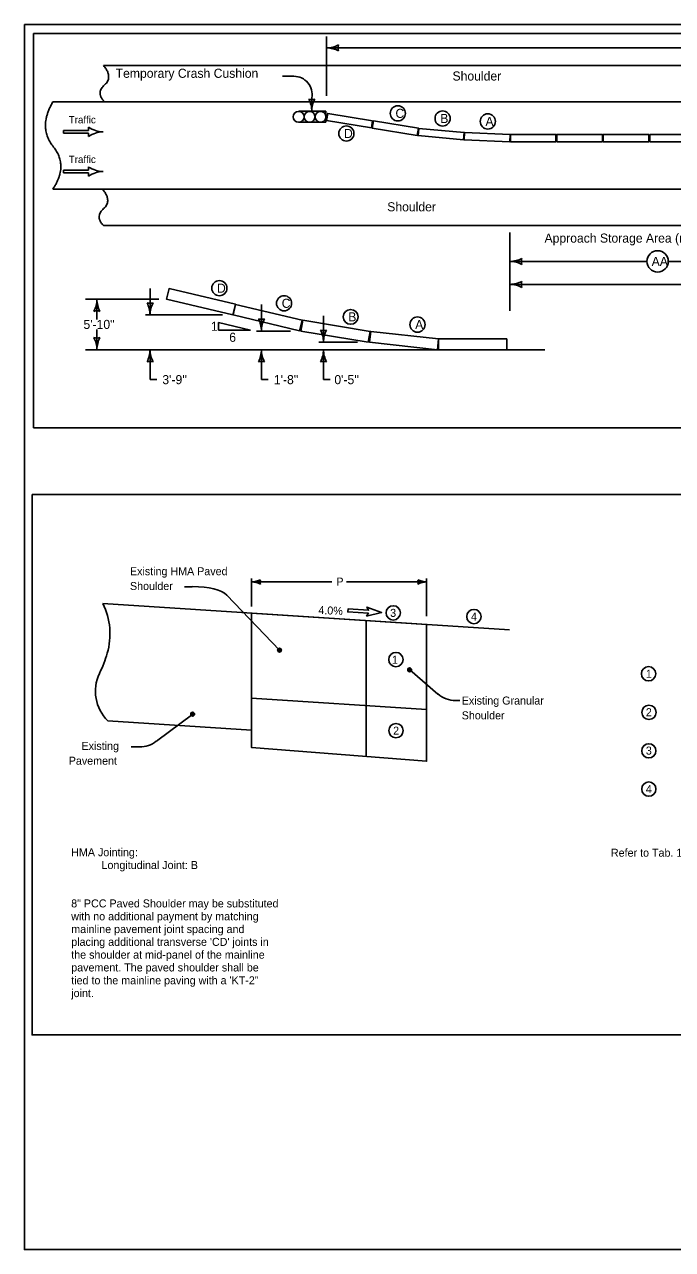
# Model space of a CAD drawing. Extents: x 8045 to 81668, y 6217 to 16762.
# Drawn here: x 13733 to 14801, y 7924 to 9944 of the extents above; entities that cross this region are included whole.
import ezdxf

# ---------------------------------------------------------------- set-up
doc = ezdxf.new("R2010")
doc.units = 0
for name, color, linetype in [('dsnNonPlotable', 7, 'Continuous'), ('dsnStdBlock', 7, 'Continuous'), ('dsnStdBlockModified', 7, 'Continuous'), ('dsnStdBorder', 7, 'Continuous'), ('dsnStdLineWork', 7, 'Continuous'), ('dsnStdNameDate', 7, 'Continuous'), ('dsnStdSection', 7, 'Continuous'), ('Level 5', 7, 'Continuous')]:
    doc.layers.add(name, color=color, linetype=linetype)

msp = doc.modelspace()

# ---------------------------------------------------------------- linework, layer by layer
at = {"layer": 'dsnNonPlotable'}
for p, q in [((14230.5, 9924.1), (14230.5, 9826.6)), ((14230.5, 9905.4), (15109, 9905.4)), ((13862.8, 9876.4), (14991.3, 9876.4)), ((14176.7, 9858.7), (14158, 9858.7)), ((14206.2, 9823.4), (14206.2, 9800.9)), ((13779.2, 9816.4), (15021.3, 9816.4)), ((14184.6, 9800.9), (14229.6, 9800.9)), ((14229.6, 9800.9), (14229.6, 9782.8)), ((14229.6, 9782.8), (14184.6, 9782.8)), ((14228.4, 9788.6), (14229.7, 9788.3)), ((14230.1, 9784.9), (14230.1, 9784.9)), ((13838.1, 9769.3), (13796.8, 9769.3)), ((13796.8, 9769.3), (13796.8, 9764.8)), ((13796.8, 9764.8), (13838.1, 9764.8)), ((13838.1, 9774.5), (13838.1, 9769.3)), ((13838.1, 9764.8), (13838.1, 9759.5)), ((13862, 9767), (13862, 9767)), ((13838.1, 9703.8), (13796.8, 9703.8)), ((13796.8, 9703.8), (13796.8, 9699.3)), ((13796.8, 9699.3), (13838.1, 9699.3)), ((13838.1, 9709.1), (13838.1, 9703.8)), ((13838.1, 9699.3), (13838.1, 9694.1)), ((13862, 9701.6), (13862, 9701.6)), ((13779.2, 9672.4), (15021.3, 9672.4)), ((13862.8, 9612.4), (14991.3, 9612.4)), ((14532.6, 9601.2), (14532.6, 9472)), ((14532.6, 9553.4), (14758.7, 9553.4)), ((14794, 9553.4), (15020.1, 9553.4)), ((14532.6, 9515.5), (15123.4, 9515.5)), ((13939.5, 9508.5), (13939.5, 9465)), ((13954.1, 9491), (13832.9, 9491)), ((13851.9, 9491), (13851.9, 9457.5)), ((14123.1, 9482.1), (14123.1, 9438.6)), ((14059, 9465), (13931.8, 9465)), ((14225.5, 9463.5), (14225.5, 9420.1)), ((13851.9, 9441.2), (13851.9, 9407.7)), ((14170.9, 9438.6), (14115.3, 9438.6)), ((14281.8, 9420.1), (14217.7, 9420.1)), ((14590.3, 9407.7), (13832.9, 9407.7)), ((13939.5, 9407.7), (13939.5, 9358.5)), ((14123.1, 9407.7), (14123.1, 9358.5)), ((14225.5, 9407.7), (14225.5, 9380.8)), ((14225.5, 9380.8), (14225.5, 9358.5)), ((13939.5, 9358.5), (13950.7, 9358.5)), ((14123.1, 9358.5), (14134.3, 9358.5)), ((14225.5, 9358.5), (14236.6, 9358.5))]:
    msp.add_line(p, q, dxfattribs=at)
for points in [[(14306.4, 9785.3), (14232.4, 9797.4), (14230.5, 9785.6), (14304.5, 9773.4)], [(14381.9, 9772.9), (14307.9, 9785), (14306, 9773.2), (14380, 9761)], [(14457.3, 9765.7), (14382.7, 9772.8), (14381.5, 9760.8), (14456.2, 9753.7)], [(14533.1, 9762.7), (14458.2, 9765.7), (14457.7, 9753.7), (14532.6, 9750.7)], [(14533.8, 9762.7), (14608.8, 9762.7), (14608.8, 9750.7), (14533.8, 9750.7)], [(14610.3, 9762.7), (14685.3, 9762.7), (14685.3, 9750.7), (14610.3, 9750.7)], [(14686.8, 9762.7), (14761.8, 9762.7), (14761.8, 9750.7), (14686.8, 9750.7)], [(14763.3, 9762.7), (14838.3, 9762.7), (14838.3, 9750.7), (14763.3, 9750.7)], [(14080.3, 9482.6), (13970.9, 9508.5), (13966.7, 9491), (14076.2, 9465.1)], [(14190.1, 9456.6), (14080.6, 9482.5), (14076.5, 9465), (14186, 9439.1)], [(14302.2, 9437.9), (14191.2, 9456.4), (14188.3, 9438.6), (14299.2, 9420.2)], [(14415.3, 9425.6), (14303.5, 9437.9), (14301.5, 9420.1), (14413.3, 9407.7)], [(14527.8, 9425.7), (14415.3, 9425.7), (14415.3, 9407.7), (14527.8, 9407.7)]]:
    msp.add_lwpolyline(points, close=True, dxfattribs=at)
for centre, radius in [((14184.6, 9791.8), 9), ((14184.6, 9791.8), 9), ((14202.6, 9791.8), 9), ((14202.6, 9791.8), 9), ((14220.6, 9791.8), 9), ((14220.6, 9791.8), 9), ((14348.1, 9797.5), 12.5), ((14421.9, 9789.1), 12.5), ((14263.2, 9764.3), 12.5), ((14496.4, 9784.2), 12.5), ((14776.4, 9553.4), 17.6), ((14053.8, 9509.2), 12.5), ((14160.5, 9484.3), 12.5), ((14270.2, 9461.9), 12.2), ((14380.5, 9449.2), 12.5)]:
    msp.add_circle(centre, radius, dxfattribs=at)
for centre, radius, start, end in [((14230.5, 9947.9), 42.5, 270, 298.0725), ((14230.5, 9862.9), 42.5, 61.9275, 90), ((14266.1, 9905.4), 16.4, 162.2666, 197.7334), ((14176.7, 9828.7), 30, 349.6463, 90), ((14206.2, 9836.5), 16.4, 252.2666, 287.7333), ((14163.7, 9800.9), 42.5, 360, 28.0725), ((14248.7, 9800.9), 42.5, 151.9275, 180), ((13864, 9815.4), 48.4, 237.618, 267.648), ((13864, 9718.7), 48.4, 92.352, 122.382), ((13864, 9749.9), 48.4, 237.618, 267.648), ((13864, 9653.3), 48.4, 92.352, 122.382), ((14532.6, 9595.9), 42.5, 270, 298.0725), ((14568.3, 9553.4), 16.4, 162.2666, 197.7334), ((14532.6, 9510.9), 42.5, 61.9275, 90), ((14532.6, 9558), 42.5, 270, 298.0725), ((14532.6, 9473), 42.5, 61.9275, 90), ((14568.3, 9515.5), 16.4, 162.2666, 197.7334), ((13809.4, 9491), 42.5, 331.9275, 0), ((13894.4, 9491), 42.5, 180, 208.0725), ((13939.5, 9500.7), 16.4, 252.2666, 287.7334), ((13897, 9465), 42.5, 0, 28.0725), ((13982, 9465), 42.5, 151.9275, 180), ((13851.9, 9455.4), 16.4, 72.2666, 107.7334), ((14123.1, 9474.3), 16.4, 252.2666, 287.7334), ((14080.6, 9438.6), 42.5, 0, 28.0725), ((14165.6, 9438.6), 42.5, 151.9275, 180), ((14225.5, 9455.7), 16.4, 252.2666, 287.7334), ((14183, 9420.1), 42.5, 0, 28.0725), ((14268, 9420.1), 42.5, 151.9275, 180), ((13851.9, 9443.4), 16.4, 252.2666, 287.7334), ((13809.4, 9407.7), 42.5, 0, 28.0725), ((13894.4, 9407.7), 42.5, 151.9275, 180), ((13897, 9407.7), 42.5, 331.9275, 0), ((13982, 9407.7), 42.5, 180, 208.0725), ((14080.6, 9407.7), 42.5, 331.9275, 0), ((14165.6, 9407.7), 42.5, 180, 208.0725), ((14183, 9407.7), 42.5, 331.9275, 0), ((14268, 9407.7), 42.5, 180, 208.0725), ((13939.5, 9372.1), 16.4, 72.2666, 107.7334), ((14123.1, 9372.1), 16.4, 72.2666, 107.7334), ((14225.5, 9372.1), 16.4, 72.2666, 107.7334)]:
    msp.add_arc(centre, radius, start, end, dxfattribs=at)
for points in [[(13862.8, 9876.4), (13878.9, 9857.1), (13850, 9831.5), (13864.4, 9816.5)], [(13779.2, 9816.4), (13754.6, 9773.8), (13805.3, 9711.6), (13779.2, 9672.4)], [(13861.2, 9672.4), (13877.3, 9653.1), (13848.4, 9627.5), (13862.8, 9612.4)]]:
    msp.add_open_spline(points, degree=2, dxfattribs=at)
at = {"layer": 'dsnStdBlock'}
msp.add_line((13747.5, 9929), (13747.5, 9929), dxfattribs=at)
at = {"layer": 'dsnStdBlockModified'}
for p, q in [((13747.5, 9929), (16852.5, 9929)), ((13747.5, 9279), (13747.5, 9929))]:
    msp.add_line(p, q, dxfattribs=at)
at = {"layer": 'dsnStdBorder'}
msp.add_line((16852.5, 9279), (13747.5, 9279), dxfattribs=at)
at = {"layer": 'dsnStdLineWork'}
for p, q in [((14107, 8984.2), (14107, 9030.4)), ((14395.5, 8968.1), (14395.5, 9030.4)), ((13996.4, 9017), (14009.1, 9017)), ((14107, 9024.9), (14239.3, 9024.9)), ((14107.1, 9024.9), (14120.9, 9024.9)), ((14263.2, 9024.9), (14395.5, 9024.9)), ((14395.5, 9024.9), (14381.7, 9024.9)), ((13861.7, 8989.1), (14532, 8945.8)), ((14066.1, 9003.2), (14153.2, 8912.4)), ((14295.8, 8736.8), (14295.8, 8961)), ((14414.1, 8840), (14367.8, 8879.7)), ((14107, 8832.9), (14395.5, 8814.2)), ((14450.3, 8829.2), (14443.4, 8829.2)), ((13869.8, 8795.8), (14107, 8780.5)), ((13949.9, 8762), (14009.9, 8807)), ((13922.4, 8752.7), (13908.4, 8752.7))]:
    msp.add_line(p, q, dxfattribs=at)
for points in [[(14120.6, 9022.3), (14120.1, 9024.9), (14120.6, 9027.5), (14117.5, 9026), (14112.6, 9024.9), (14117.9, 9023.6), (14120.2, 9022.6), (14119.6, 9024.9), (14119.8, 9026.5), (14117.8, 9025.6), (14115.1, 9024.9), (14118, 9024), (14119.5, 9023.5), (14119.2, 9025.7), (14117.2, 9024.9), (14118.8, 9024.4), (14118.8, 9025.1), (14118.1, 9024.9)], [(14382, 9027.4), (14382.5, 9024.8), (14382, 9022.2), (14385.1, 9023.7), (14390, 9024.8), (14384.7, 9026.1), (14382.4, 9027.1), (14383, 9024.8), (14382.8, 9023.2), (14384.8, 9024.1), (14387.5, 9024.8), (14384.6, 9025.7), (14383.1, 9026.2), (14383.4, 9024), (14385.4, 9024.8), (14383.8, 9025.3), (14383.8, 9024.6), (14384.5, 9024.8)], [(14107, 8973.5), (14107, 8751.6), (14395.5, 8729), (14395.5, 8954.6)], [(14155.2, 8914.1), (14154.2, 8914.5), (14152.6, 8915.3), (14151.2, 8914.3), (14150.3, 8913.1), (14150.1, 8911.4), (14151.3, 8910.4), (14152.7, 8909.4), (14154.2, 8909.8), (14155.3, 8910.7), (14155.8, 8912.6), (14155.1, 8913.6), (14153.6, 8914.5), (14151.9, 8914.7), (14150.8, 8913.5), (14150.7, 8911.9), (14151.6, 8910.7), (14153, 8909.8), (14153.9, 8910.3), (14154.9, 8910.8), (14155.3, 8912.4), (14154.5, 8913.2), (14153.3, 8914), (14152.1, 8914.2), (14151.5, 8912.8), (14151.6, 8911.5), (14152.6, 8910.5), (14153.3, 8910.8), (14154.3, 8911.1), (14154.5, 8912.3), (14154, 8913.2), (14153, 8913.5), (14152.2, 8912.9), (14152.1, 8912), (14152.6, 8911.2), (14153.1, 8911.1), (14153.7, 8911.3), (14154, 8912.3), (14153.6, 8912.8), (14152.9, 8913), (14152.6, 8912.5), (14152.7, 8912), (14153.1, 8911.5), (14153.4, 8911.8), (14153.2, 8912.4)], [(14369.7, 8881.7), (14368.6, 8882.1), (14367.1, 8882.9), (14365.7, 8881.9), (14364.8, 8880.7), (14364.6, 8879), (14365.8, 8878), (14367.1, 8877), (14368.6, 8877.4), (14369.7, 8878.3), (14370.3, 8880.2), (14369.6, 8881.2), (14368.1, 8882.1), (14366.4, 8882.3), (14365.3, 8881.1), (14365.2, 8879.5), (14366.1, 8878.4), (14367.5, 8877.4), (14368.3, 8877.9), (14369.4, 8878.4), (14369.8, 8880), (14368.9, 8880.8), (14367.8, 8881.6), (14366.5, 8881.8), (14365.9, 8880.4), (14366.1, 8879.1), (14367, 8878.1), (14367.8, 8878.4), (14368.7, 8878.7), (14369, 8879.9), (14368.5, 8880.8), (14367.5, 8881.1), (14366.7, 8880.5), (14366.5, 8879.6), (14367, 8878.8), (14367.6, 8878.7), (14368.2, 8878.9), (14368.4, 8879.9), (14368.1, 8880.4), (14367.3, 8880.6), (14367, 8880.1), (14367.1, 8879.6), (14367.6, 8879.1), (14367.9, 8879.5), (14367.7, 8880)], [(14011.9, 8808.7), (14010.8, 8809.1), (14009.3, 8809.9), (14007.9, 8808.9), (14007, 8807.7), (14006.8, 8806), (14008, 8805), (14009.3, 8804), (14010.8, 8804.3), (14011.9, 8805.2), (14012.5, 8807.2), (14011.8, 8808.2), (14010.3, 8809), (14008.6, 8809.3), (14007.5, 8808.1), (14007.4, 8806.5), (14008.3, 8805.3), (14009.7, 8804.4), (14010.6, 8804.9), (14011.6, 8805.4), (14012, 8806.9), (14011.1, 8807.8), (14010, 8808.6), (14008.7, 8808.7), (14008.1, 8807.4), (14008.3, 8806.1), (14009.2, 8805.1), (14010, 8805.4), (14010.9, 8805.7), (14011.2, 8806.9), (14010.7, 8807.8), (14009.7, 8808.1), (14008.9, 8807.4), (14008.7, 8806.6), (14009.2, 8805.7), (14009.8, 8805.7), (14010.4, 8805.9), (14010.6, 8806.8), (14010.3, 8807.4), (14009.6, 8807.6), (14009.2, 8807.1), (14009.3, 8806.5), (14009.8, 8806.1), (14010.1, 8806.4), (14009.9, 8807)]]:
    msp.add_lwpolyline(points, dxfattribs=at)
for points in [[(14107, 8973.5), (14395.5, 8954.6), (14395.5, 8814.2), (14107, 8832.9)], [(14296.3, 8968.2), (14321.3, 8974.4), (14297.2, 8983.4), (14299.8, 8978.2), (14266, 8980.4), (14265.6, 8975.3), (14299.5, 8973.1)]]:
    msp.add_lwpolyline(points, close=True, dxfattribs=at)
for centre, radius in [((14340.5, 8973.8), 11.8), ((14473.5, 8967.7), 11.8), ((14153, 8912.2), 3.15), ((14344.9, 8896.8), 11.8), ((14367.5, 8879.8), 3.15), ((14761.5, 8873.4), 11.8), ((14009.7, 8806.8), 3.15), ((14762.1, 8809.7), 11.8), ((14345, 8779.6), 11.8), ((14761.9, 8746.3), 11.8), ((14761.9, 8683.2), 11.8)]:
    msp.add_circle(centre, radius, dxfattribs=at)
for centre, radius, start, end in [((14107.1, 9055.5), 30.6, 270, 298.0725), ((14107.1, 8994.3), 30.6, 61.9275, 90), ((14132.7, 9024.9), 11.8, 162.2666, 197.7334), ((14369.9, 9024.9), 11.8, 342.2666, 17.7334), ((14395.5, 9055.5), 30.6, 241.9275, 270), ((14395.5, 8994.3), 30.6, 90, 118.0725), ((13760.4, 8939), 113, 343.6708, 26.3373), ((13656.4, 8969.5), 221.4, 334.4332, 343.6708), ((13917.6, 8844.5), 68.2, 154.4332, 225.5564), ((14443.4, 8874.2), 45, 229.3882, 270), ((13922.4, 8797.7), 45, 270, 307.6187)]:
    msp.add_arc(centre, radius, start, end, dxfattribs=at)
msp.add_ellipse((13953.9, 8972), major_axis=(-116.2, -24), ratio=0.327877, start_param=3.345066, end_param=4.150713, dxfattribs=at)
at = {"layer": 'dsnStdNameDate'}
msp.add_lwpolyline([(13745, 9169.2), (15295.8, 9169.2), (15295.8, 8277.8), (13745, 8277.8)], close=True, dxfattribs=at)
at = {"layer": 'dsnStdSection'}
msp.add_lwpolyline([(13732.5, 9944), (16867.5, 9944), (16867.5, 7924), (13732.5, 7924)], close=True, dxfattribs=at)
at = {"layer": 'Level 5'}
for p, q in [((14105.1, 9440.1), (14052.5, 9452.5)), ((14052.5, 9452.5), (14052.5, 9440.1)), ((14052.5, 9440.1), (14105.1, 9440.1))]:
    msp.add_line(p, q, dxfattribs=at)

# ---------------------------------------------------------------- texts
at = {"layer": 'dsnStdLineWork'}
for s, p in [('Existing HMA Paved', (13906.4, 9035.9)), ('P', (14246.7, 9018.8)), ('Shoulder', (13906.4, 9011.5)), ('3', (14335.4, 8967.2)), ('4', (14468.7, 8961.1)), ('1', (14338.4, 8889.9)), ('1', (14757, 8866.8)), ('Existing Granular', (14453.4, 8822.6)), ('Shoulder', (14453.4, 8798.2)), ('2', (14757, 8803.4)), ('2', (14340.3, 8773)), ('Existing', (13826.5, 8747.8)), ('3', (14757, 8740.1)), ('Pavement', (13805.5, 8723.4)), ('4', (14757, 8676.7)), ('HMA Jointing:', (13809.5, 8572.5)), ('Refer to Tab. 112-9 for P width and Shoulder quantities', (14699.4, 8571.7)), ('Longitudinal Joint: B', (13859.5, 8551.4)), ('8" PCC Paved Shoulder may be substituted', (13809.5, 8488.1)), ('with no additional payment by matching ', (13809.5, 8466.9)), ('mainline pavement joint spacing and ', (13809.6, 8445.8)), ("placing additional transverse 'CD' joints in ", (13809.6, 8424.7)), ('the shoulder at mid-panel of the mainline ', (13809.6, 8403.6)), ('pavement. The paved shoulder shall be ', (13809.6, 8382.5)), ('tied to the mainline paving with a \'KT-2" ', (13809.6, 8361.3)), ('joint.', (13809.6, 8340.2))]:
    msp.add_text(s, height=13.2, dxfattribs=at).set_placement(p)
msp.add_text('4.0%', height=13.2, rotation=357.4961, dxfattribs=at).set_placement((14216.8, 8972))
at = {"layer": 'Level 5'}
for s, height, p in [('Temporary Crash Cushion', 15, (13882.8, 9856.1)), ('Shoulder', 15, (14438.2, 9851.6)), ('C', 15, (14344.2, 9790)), ('Traffic', 12, (13805.5, 9781)), ('B', 15, (14418, 9781.6)), ('A', 15, (14492.5, 9776.7)), ('D', 15, (14259.3, 9756.8)), ('Traffic', 12, (13805.5, 9715.6)), ('Shoulder', 15, (14330.6, 9635.9)), ("Approach Storage Area (minimum 20')", 15, (14589.9, 9584.3)), ('AA', 15, (14766.6, 9545.9)), ('D', 15, (14049.9, 9501.7)), ('C', 15, (14156.6, 9476.8)), ("5'-10''", 15, (13829.7, 9442)), ('1', 15, (14039.9, 9438.9)), ('B', 15, (14266.3, 9454.4)), ('A', 15, (14376.6, 9441.7)), ('6', 15, (14070.1, 9420.8)), ("3'-9''", 15, (13959.8, 9350.9)), ("1'-8''", 15, (14143.7, 9350.9)), ("0'-5''", 15, (14243.4, 9350.9))]:
    msp.add_text(s, height=height, dxfattribs=at).set_placement(p)

doc.saveas('drawing.dxf')
